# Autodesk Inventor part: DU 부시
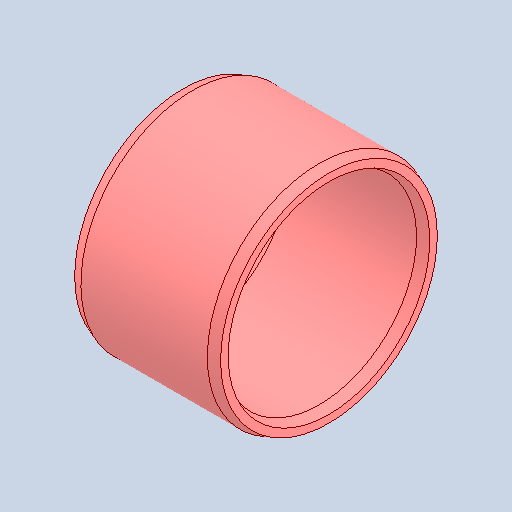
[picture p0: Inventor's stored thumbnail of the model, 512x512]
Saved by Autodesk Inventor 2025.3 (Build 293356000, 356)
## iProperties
Created: 2025-10
Part Number: DU 부시
Material: 스테인리스스틸
Document SubType Name: Modeling
Designer: PC-15
Density: 8 g/cm^3
Appearance: 기본값
Author: jhkim
Sending System: Autodesk Inventor 2026
Preprocessor: ST-DEVELOPER v20.1
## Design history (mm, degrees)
feature "솔리드1"
node "솔리드2"
